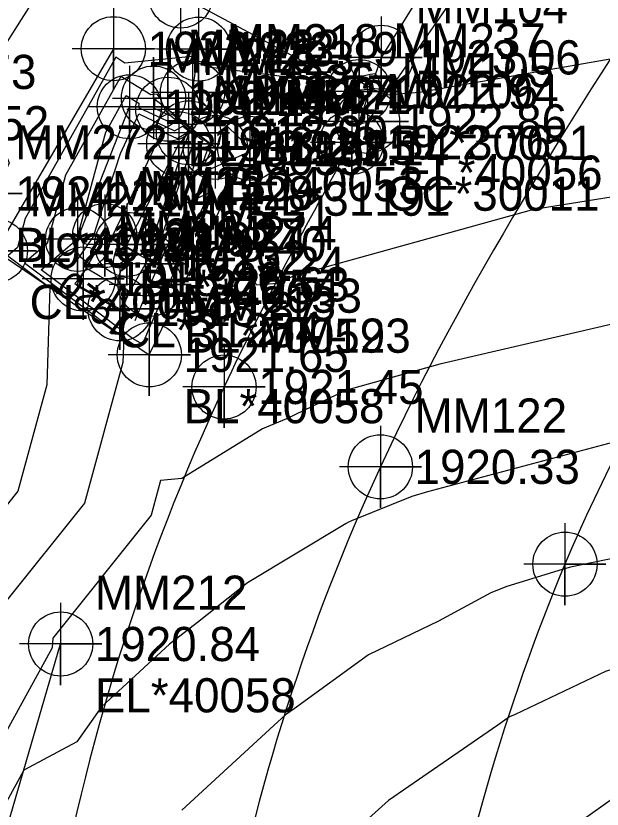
# Model space of a CAD drawing. Extents: x 1004378 to 1005103, y 553854 to 554288.
# Drawn here: x 1005001.8 to 1005044.7, y 554194.9 to 554252.9 of the extents above; entities that cross this region are included whole.
import ezdxf

# ---------------------------------------------------------------- set-up
doc = ezdxf.new("R2010")
doc.units = 0
for name, color, linetype in [('DTM Contours Major', 7, 'Continuous'), ('DTM Contours Major Text', 7, 'Continuous'), ('DTM Contours Minor', 7, 'Continuous'), ('Exist DTM Breakline', 7, 'Continuous'), ('Exist DTM Breakline Cogo Comment', 7, 'Continuous'), ('Exist DTM Breakline Cogo Elevation', 7, 'Continuous'), ('Exist DTM Breakline Cogo Number', 7, 'Continuous'), ('Exist DTM Breakline Cogo Point CELL', 7, 'Continuous'), ('Exist DTM Crownline', 7, 'Continuous'), ('Exist DTM Crownline Cogo Elevation', 7, 'Continuous'), ('Exist DTM Crownline Cogo Number', 7, 'Continuous'), ('Exist DTM Crownline Cogo Point CELL', 7, 'Continuous'), ('Exist DTM Regular Point Cogo Elevation', 7, 'Continuous'), ('Exist DTM Regular Point Cogo Number', 7, 'Continuous'), ('Exist DTM Spot Elevation Cogo Elevation', 7, 'Continuous'), ('Exist DTM Spot Elevation Cogo Number', 7, 'Continuous'), ('Exist Roads Curbs', 7, 'Continuous'), ('Exist Roads EOP', 7, 'Continuous'), ('Exist Roads EOP Cogo Comment', 7, 'Continuous'), ('Exist Roads EOP Cogo Elevation', 7, 'Continuous'), ('Exist Roads EOP Cogo Number', 7, 'Continuous'), ('Exist Roads EOP Cogo Point CELL', 7, 'Continuous'), ('Exist Roads Soil', 7, 'Continuous'), ('Exist Roads Soil Cogo Comment', 7, 'Continuous'), ('Exist Roads Soil Cogo Elevation', 7, 'Continuous'), ('Exist Roads Soil Cogo Number', 7, 'Continuous'), ('Exist Roads Soil Cogo Point CELL', 7, 'Continuous'), ('Exist Structure Major Bridge WW Cogo Comment', 7, 'Continuous'), ('Exist Structure Major Bridge WW Cogo Elevation', 7, 'Continuous'), ('Exist Structure Major Bridge WW Cogo Number', 7, 'Continuous'), ('Exist Structure Major Bridge WW Cogo Point CELL', 7, 'Continuous'), ('Exist Structure Minor Drop Inlet Cogo Comment', 7, 'Continuous'), ('Exist Structure Minor Drop Inlet Cogo Elevation', 7, 'Continuous'), ('Exist Structure Minor Drop Inlet Cogo Number', 7, 'Continuous'), ('Exist Structure Minor Drop Inlet Cogo Point CELL', 7, 'Continuous')]:
    doc.layers.add(name, color=color, linetype=linetype)

msp = doc.modelspace()

# ---------------------------------------------------------------- linework, layer by layer
at = {"layer": 'DTM Contours Major'}
for points in [[(1005005.579, 554234.428), (1005006.321, 554235.061), (1005007.473, 554236.739), (1005009.471, 554242.852), (1005010.83, 554245.746)], [(1005010.83, 554245.746), (1005013.438, 554244.516), (1005014.032, 554244.854), (1005015.001, 554244.074), (1005014.744, 554243.464), (1005012.475, 554236.752), (1005013.363, 554237.145), (1005011.504, 554232.95), (1005010.522, 554230.625)], [(1005085.253, 554232.251), (1005065.7, 554222.397), (1005064.933, 554221.918), (1005064.991, 554222.066), (1005065.344, 554223.049), (1005065.952, 554224.718), (1005066.048, 554225.004), (1005062.678, 554224.698), (1005047.268, 554222.206), (1005031.925, 554218.126), (1005030.77, 554217.777), (1005026.361, 554215.994), (1005026.142, 554215.905), (1005025.965, 554215.797), (1005018.761, 554211.473), (1005015.099, 554208.571), (1005013.055, 554206.965), (1005008.097, 554202.389), (1005006.285, 554199.827), (1005002.41, 554197.77), (1005001.113, 554195.406)]]:
    msp.add_lwpolyline(points, dxfattribs=at)
at = {"layer": 'DTM Contours Minor'}
for points in [[(1005049.674, 554261.493), (1005048.336, 554262.162), (1005048.391, 554261.154), (1005047.971, 554261.002), (1005047.219, 554261.151), (1005038.078, 554260.42), (1005037.81, 554261.029), (1005038.533, 554264.244), (1005038.474, 554264.547), (1005022.134, 554266.393), (1005018.739, 554266.663), (1005008.512, 554259.857), (1005006.97, 554257.736), (1005007.666, 554257.334), (1005003.478, 554254.686), (1004999.082, 554247.727), (1005001.345, 554242.184), (1004999.666, 554238.402), (1004998.854, 554234.12), (1004998.544, 554224.321), (1004997.101, 554219.058), (1004994.148, 554215.354), (1004993.153, 554201.493), (1004985.717, 554187.945)], [(1005045.835, 554249.855), (1005031.335, 554247.323), (1005028.865, 554247.126), (1005028.25, 554248.522), (1005028.121, 554248.671), (1005027.728, 554248.629), (1005025.559, 554248.116), (1005024.184, 554248.111), (1005015.878, 554249.159), (1005015.053, 554249.514), (1005014.698, 554249.961), (1005009.806, 554249.475), (1005009.131, 554249.89), (1005002.516, 554238.096), (1005001.94, 554235.973), (1005001.24, 554235.376), (1005004.325, 554233.049), (1005004.1, 554225.944), (1005001.971, 554218.176), (1004997.612, 554212.709), (1004996.931, 554203.23), (1004987.915, 554186.802)], [(1005058.295, 554241.729), (1005039.877, 554238.78), (1005039.335, 554238.654), (1005022.102, 554233.882), (1005020.992, 554233.342), (1005019.427, 554233.237), (1005016.782, 554238.803), (1005018.564, 554242.826), (1005015.241, 554241.355), (1005015.916, 554243.352), (1005015.992, 554243.533), (1005013.267, 554245.727), (1005013.091, 554245.626), (1005011.963, 554246.158), (1005012.004, 554246.821), (1005012.332, 554246.974), (1005012.153, 554247.198), (1005011.692, 554247.152), (1005009.516, 554248.491), (1005005.462, 554241.262), (1005004.108, 554236.273), (1005002.462, 554234.869), (1005009.715, 554229.399), (1005009.657, 554227.567), (1005006.84, 554217.294), (1005001.076, 554210.065)], [(1005013.264, 554245.071), (1005013.649, 554245.29), (1005015.496, 554243.804), (1005015.33, 554243.408), (1005013.858, 554239.054), (1005015.963, 554239.985), (1005011.554, 554230.034), (1005011.084, 554228.92), (1005010.348, 554229.337), (1005003.685, 554234.362), (1005006.277, 554236.572), (1005008.408, 554244.428), (1005009.901, 554247.092), (1005010.821, 554246.526), (1005010.803, 554246.232), (1005013.264, 554245.071)], [(1005009.801, 554238.687), (1005012.52, 554244.475), (1005013.612, 554243.96), (1005014.414, 554244.418), (1005014.505, 554244.345), (1005014.159, 554243.52), (1005012.088, 554237.397), (1005010.992, 554235.429), (1005008.828, 554236.656), (1005009.801, 554238.687)], [(1005081.907, 554236.456), (1005081.575, 554236.342), (1005069.531, 554230.299), (1005070.085, 554231.824), (1005070.64, 554233.472), (1005054.504, 554232.01), (1005052.782, 554231.968), (1005051.198, 554231.714), (1005032.836, 554227.453), (1005025.92, 554225.538), (1005021.623, 554223.448), (1005019.859, 554222.732), (1005013.96, 554219.101), (1005012.402, 554218.937), (1005011.71, 554216.413), (1005004.54, 554207.42), (1005004.489, 554206.704), (1004992.311, 554184.516)], [(1005006.967, 554234.467), (1005006.297, 554233.491), (1005006.13, 554233.348), (1005006.549, 554233.032), (1005009.541, 554231.336), (1005010.106, 554232.675), (1005008.005, 554233.874), (1005006.967, 554234.467)], [(1005080.939, 554224.769), (1005067.37, 554217.93), (1005060.336, 554213.536), (1005060.866, 554214.898), (1005061.455, 554216.534), (1005042.381, 554212.616), (1005041.766, 554212.425), (1005037.72, 554211.199), (1005036.548, 554210.725), (1005032.718, 554208.659), (1005027.609, 554206.201), (1005022.187, 554202.253), (1005021.549, 554201.814), (1005020.689, 554201.039), (1005013.957, 554194.829)], [(1005076.625, 554217.286), (1005069.041, 554213.464), (1005056.52, 554205.643), (1005056.186, 554205.45), (1005055.751, 554205.106), (1005055.8, 554205.258), (1005055.916, 554205.611), (1005056.742, 554207.729), (1005056.863, 554208.065), (1005052.951, 554207.261), (1005051.317, 554206.753), (1005044.981, 554205.003), (1005038.321, 554201.832), (1005037.92, 554201.653), (1005037.066, 554201.044), (1005029.069, 554195.542), (1005025.438, 554192.269)], [(1005072.311, 554209.804), (1005070.712, 554208.998), (1005068.073, 554207.35), (1005060.854, 554203.169), (1005055.614, 554199.027), (1005051.563, 554195.07), (1005051.936, 554196.712), (1005052.473, 554198.935), (1005052.494, 554198.998), (1005052.502, 554199.025), (1005052.396, 554198.996), (1005052.336, 554198.967), (1005046.282, 554196.261), (1005040.238, 554191.952)]]:
    msp.add_lwpolyline(points, dxfattribs=at)
at = {"layer": 'Exist DTM Breakline'}
msp.add_line((1005041.953, 554266.011), (1005027.535, 554245.207), dxfattribs=at)
for points in [[(1005011.587, 554228.131), (1005018.939, 554243.236), (1005014.748, 554247.317), (1005015.189, 554250.493), (1005008.958, 554250.519), (1005000.334, 554235.751), (1005011.587, 554228.131)], [(1005011.889, 554246.911), (1005012.944, 554246.095), (1005016.412, 554243.304)], [(1005006.344, 554236.582), (1005010.126, 554246.275)], [(1005014.454, 554244.373), (1005013.737, 554243.561), (1005009.944, 554236.21)], [(1004987.71, 553883.194), (1004993.763, 553908.865), (1004995.956, 553952.192), (1004996.06, 553992.449), (1004993.928, 554035.876), (1004994.309, 554070.389), (1004993.033, 554080.737), (1004990.275, 554106.198), (1004991.435, 554130.882), (1004994.664, 554165.005), (1004997.714, 554181.706), (1005005.106, 554206.988)]]:
    msp.add_lwpolyline(points, dxfattribs=at)
msp.add_lwpolyline([(1005009.438, 554231.497), (1005011.467, 554235.075), (1005008.323, 554236.858), (1005006.294, 554233.28)], close=True, dxfattribs=at)
msp.add_spline([(1005062.556, 554249.275), (1005041.97, 554212.824), (1005032.11, 554179.915), (1005026.833, 554146.301), (1005025.779, 554104.318), (1005027.497, 554055.674)], degree=3, dxfattribs=at)
at = {"layer": 'Exist DTM Breakline Cogo Point CELL'}
for points in [[(1005008.958, 554253.519), (1005008.958, 554247.519), (1005008.958, 554250.519), (1005011.958, 554250.519), (1005005.958, 554250.519)], [(1005015.189, 554253.493), (1005015.189, 554247.493), (1005015.189, 554250.493), (1005018.189, 554250.493), (1005012.189, 554250.493)], [(1005014.748, 554250.317), (1005014.748, 554244.317), (1005014.748, 554247.317), (1005017.748, 554247.317), (1005011.748, 554247.317)], [(1005010.126, 554249.275), (1005010.126, 554243.275), (1005010.126, 554246.275), (1005013.126, 554246.275), (1005007.126, 554246.275)], [(1005027.535, 554248.207), (1005027.535, 554242.207), (1005027.535, 554245.207), (1005030.535, 554245.207), (1005024.535, 554245.207)], [(1005014.454, 554247.373), (1005014.454, 554241.373), (1005014.454, 554244.373), (1005017.454, 554244.373), (1005011.454, 554244.373)], [(1005013.737, 554246.561), (1005013.737, 554240.561), (1005013.737, 554243.561), (1005016.737, 554243.561), (1005010.737, 554243.561)], [(1005018.939, 554246.236), (1005018.939, 554240.236), (1005018.939, 554243.236), (1005021.939, 554243.236), (1005015.939, 554243.236)], [(1004999.282, 554242.926), (1004999.282, 554236.926), (1004999.282, 554239.926), (1005002.282, 554239.926), (1004996.282, 554239.926)], [(1005006.344, 554239.582), (1005006.344, 554233.582), (1005006.344, 554236.582), (1005009.344, 554236.582), (1005003.344, 554236.582)], [(1005000.334, 554238.751), (1005000.334, 554232.751), (1005000.334, 554235.751), (1005003.334, 554235.751), (1004997.334, 554235.751)], [(1005009.944, 554239.21), (1005009.944, 554233.21), (1005009.944, 554236.21), (1005012.944, 554236.21), (1005006.944, 554236.21)], [(1005011.643, 554236.289), (1005011.643, 554230.289), (1005011.643, 554233.289), (1005014.643, 554233.289), (1005008.643, 554233.289)], [(1005011.587, 554231.131), (1005011.587, 554225.131), (1005011.587, 554228.131), (1005014.587, 554228.131), (1005008.587, 554228.131)], [(1005041.97, 554215.824), (1005041.97, 554209.824), (1005041.97, 554212.824), (1005044.97, 554212.824), (1005038.97, 554212.824)], [(1005005.106, 554209.988), (1005005.106, 554203.988), (1005005.106, 554206.988), (1005008.106, 554206.988), (1005002.106, 554206.988)]]:
    msp.add_lwpolyline(points, dxfattribs=at)
for centre in [(1005008.958, 554250.519), (1005015.189, 554250.493), (1005014.748, 554247.317), (1005010.126, 554246.275), (1005027.535, 554245.207), (1005014.454, 554244.373), (1005013.737, 554243.561), (1005018.939, 554243.236), (1005006.344, 554236.582), (1005009.944, 554236.21), (1005000.334, 554235.751), (1005011.643, 554233.289), (1005011.587, 554228.131), (1005041.97, 554212.824), (1005005.106, 554206.988)]:
    msp.add_circle(centre, 2.344, dxfattribs=at)
at = {"layer": 'Exist DTM Crownline'}
msp.add_spline([(1005050.587, 554258.044), (1005028.479, 554219.945), (1005017.046, 554183.931), (1005013.967, 554147.492), (1005013.771, 554103.753), (1005015.769, 554055.214)], degree=3, dxfattribs=at)
at = {"layer": 'Exist DTM Crownline Cogo Point CELL'}
msp.add_lwpolyline([(1005028.479, 554222.945), (1005028.479, 554216.945), (1005028.479, 554219.945), (1005031.479, 554219.945), (1005025.479, 554219.945)], dxfattribs=at)
msp.add_circle((1005028.479, 554219.945), 2.344, dxfattribs=at)
at = {"layer": 'Exist Roads Curbs'}
msp.add_spline([(1005075.03, 554240.325), (1005055.961, 554205.561), (1005046.997, 554176.639), (1005041.862, 554143.203), (1005041.439, 554133.575)], degree=3, dxfattribs=at)
at = {"layer": 'Exist Roads EOP'}
msp.add_lwpolyline([(1005042.326, 554267.369), (1005036.922, 554263.41), (1005028.544, 554249.886), (1005026.381, 554243.671)], dxfattribs=at)
for points in [[(1005026.381, 554243.671), (1005017.049, 554225.785), (1005004.478, 554185.698), (1005001.445, 554147.868), (1005001.025, 554103.612), (1005002.785, 554054.517)], [(1005074.494, 554240.581), (1005055.678, 554205.88), (1005046.35, 554176.623), (1005041.386, 554143.248), (1005040.93, 554132.857)]]:
    msp.add_spline(points, degree=3, dxfattribs=at)
at = {"layer": 'Exist Roads EOP Cogo Point CELL'}
for points in [[(1005028.544, 554252.886), (1005028.544, 554246.886), (1005028.544, 554249.886), (1005031.544, 554249.886), (1005025.544, 554249.886)], [(1005026.381, 554246.671), (1005026.381, 554240.671), (1005026.381, 554243.671), (1005029.381, 554243.671), (1005023.381, 554243.671)], [(1005017.049, 554228.785), (1005017.049, 554222.785), (1005017.049, 554225.785), (1005020.049, 554225.785), (1005014.049, 554225.785)]]:
    msp.add_lwpolyline(points, dxfattribs=at)
for centre in [(1005028.544, 554249.886), (1005026.381, 554243.671), (1005017.049, 554225.785)]:
    msp.add_circle(centre, 2.344, dxfattribs=at)
at = {"layer": 'Exist Roads Soil'}
msp.add_lwpolyline([(1005026.922, 554247.386), (1005013.881, 554254.375), (1004980.46, 554270.626), (1004959.228, 554275.018)], dxfattribs=at)
at = {"layer": 'Exist Roads Soil Cogo Point CELL'}
for points in [[(1005013.881, 554251.375), (1005013.881, 554257.375), (1005013.881, 554254.375), (1005016.881, 554254.375), (1005010.881, 554254.375)], [(1005026.922, 554244.386), (1005026.922, 554250.386), (1005026.922, 554247.386), (1005029.922, 554247.386), (1005023.922, 554247.386)]]:
    msp.add_lwpolyline(points, dxfattribs=at)
for centre in [(1005013.881, 554254.375), (1005026.922, 554247.386)]:
    msp.add_circle(centre, 2.344, dxfattribs=at)
at = {"layer": 'Exist Structure Major Bridge WW Cogo Point CELL'}
for points in [[(1005008.889, 554246.911), (1005014.889, 554246.911), (1005011.889, 554246.911), (1005011.889, 554249.911), (1005011.889, 554243.911)], [(1005009.944, 554246.095), (1005015.944, 554246.095), (1005012.944, 554246.095), (1005012.944, 554249.095), (1005012.944, 554243.095)], [(1005013.412, 554243.304), (1005019.412, 554243.304), (1005016.412, 554243.304), (1005016.412, 554246.304), (1005016.412, 554240.304)]]:
    msp.add_lwpolyline(points, dxfattribs=at)
for centre in [(1005011.889, 554246.911), (1005012.944, 554246.095), (1005016.412, 554243.304)]:
    msp.add_circle(centre, 2.344, dxfattribs=at)
at = {"layer": 'Exist Structure Minor Drop Inlet Cogo Point CELL'}
for points in [[(1005008.323, 554239.858), (1005008.323, 554233.858), (1005008.323, 554236.858), (1005011.323, 554236.858), (1005005.323, 554236.858)], [(1005011.304, 554237.786), (1005011.304, 554231.786), (1005011.304, 554234.786), (1005014.304, 554234.786), (1005008.304, 554234.786)], [(1005006.752, 554236.683), (1005006.752, 554230.683), (1005006.752, 554233.683), (1005009.752, 554233.683), (1005003.752, 554233.683)], [(1005009.438, 554234.497), (1005009.438, 554228.497), (1005009.438, 554231.497), (1005012.438, 554231.497), (1005006.438, 554231.497)]]:
    msp.add_lwpolyline(points, dxfattribs=at)
for centre in [(1005008.323, 554236.858), (1005011.304, 554234.786), (1005006.752, 554233.683), (1005009.438, 554231.497)]:
    msp.add_circle(centre, 2.344, dxfattribs=at)

# ---------------------------------------------------------------- texts
at = {"layer": 'DTM Contours Major Text'}
msp.add_text('1920', height=2, rotation=142.43295, dxfattribs=at).set_placement((1005010.584, 554230.788))
at = {"layer": 'Exist DTM Breakline Cogo Comment'}
for s, p in [('EL*40059', (1005012.626, 554241.275)), ('EL*40056', (1005030.035, 554240.207)), ('BL*40053', (1005016.954, 554239.373)), ('BL*40051', (1005001.782, 554234.926)), ('EL*40053', (1005012.444, 554231.21)), ('CL*40058', (1005002.834, 554230.751)), ('BL*40059', (1005014.143, 554228.289)), ('BL*40058', (1005014.087, 554223.131)), ('EL*40058', (1005007.606, 554201.988))]:
    msp.add_text(s, height=2.5, dxfattribs=at).set_placement(p)
at = {"layer": 'Exist DTM Breakline Cogo Elevation'}
for s, p in [('1923.45', (1005011.458, 554249.269)), ('1923.19', (1005017.689, 554249.243)), ('1922.57', (1005017.248, 554246.067)), ('1920.42', (1005012.626, 554245.025)), ('1922.86', (1005030.035, 554243.957)), ('1918.90', (1005016.954, 554243.123)), ('1918.28', (1005016.237, 554242.311)), ('1922.14', (1005021.439, 554241.986)), ('1924.15', (1005001.782, 554238.676)), ('1920.97', (1005008.844, 554235.332)), ('1923.74', (1005002.834, 554234.501)), ('1918.40', (1005012.444, 554234.96)), ('1920.63', (1005014.143, 554232.039)), ('1921.65', (1005014.087, 554226.881)), ('1920.84', (1005007.606, 554205.738))]:
    msp.add_text(s, height=2.5, dxfattribs=at).set_placement(p)
at = {"layer": 'Exist DTM Breakline Cogo Number'}
for s, p in [('MM218', (1005017.248, 554249.817)), ('MM216', (1005012.626, 554248.775)), ('MM105', (1005030.035, 554247.707)), ('MM226', (1005016.954, 554246.873)), ('MM227', (1005016.237, 554246.061)), ('MM217', (1005021.439, 554245.736)), ('MM272', (1005001.782, 554242.426)), ('MM215', (1005008.844, 554239.082)), ('MM228', (1005012.444, 554238.71)), ('MM221', (1005002.834, 554238.251)), ('MM214', (1005014.143, 554235.789)), ('MM213', (1005014.087, 554230.631)), ('MM212', (1005007.606, 554209.488))]:
    msp.add_text(s, height=2.5, dxfattribs=at).set_placement(p)
at = {"layer": 'Exist DTM Crownline Cogo Elevation'}
msp.add_text('1920.33', height=2.5, dxfattribs=at).set_placement((1005030.979, 554218.695))
at = {"layer": 'Exist DTM Crownline Cogo Number'}
msp.add_text('MM122', height=2.5, dxfattribs=at).set_placement((1005030.979, 554222.445))
at = {"layer": 'Exist DTM Regular Point Cogo Elevation'}
msp.add_text('1924.52', height=2.5, dxfattribs=at).set_placement((1004992.187, 554243.822))
at = {"layer": 'Exist DTM Regular Point Cogo Number'}
msp.add_text('MM273', height=2.5, dxfattribs=at).set_placement((1004992.187, 554247.572))
at = {"layer": 'Exist DTM Spot Elevation Cogo Elevation'}
msp.add_text('1918.40', height=2.5, dxfattribs=at).set_placement((1005012.444, 554234.96))
at = {"layer": 'Exist DTM Spot Elevation Cogo Number'}
msp.add_text('MM229', height=2.5, dxfattribs=at).set_placement((1005012.444, 554238.71))
at = {"layer": 'Exist Roads EOP Cogo Comment'}
msp.add_text('OC*30011', height=2.5, dxfattribs=at).set_placement((1005028.881, 554238.671))
at = {"layer": 'Exist Roads EOP Cogo Elevation'}
for s, p in [('1923.06', (1005031.044, 554248.636)), ('1922.76', (1005028.881, 554242.421)), ('1921.45', (1005019.549, 554224.535))]:
    msp.add_text(s, height=2.5, dxfattribs=at).set_placement(p)
at = {"layer": 'Exist Roads EOP Cogo Number'}
for s, p in [('MM104', (1005031.044, 554252.386)), ('MM106', (1005028.881, 554246.171)), ('MM123', (1005019.549, 554228.285))]:
    msp.add_text(s, height=2.5, dxfattribs=at).set_placement(p)
at = {"layer": 'Exist Roads Soil Cogo Comment'}
msp.add_text('BL*30051', height=2.5, dxfattribs=at).set_placement((1005029.422, 554242.386))
at = {"layer": 'Exist Roads Soil Cogo Elevation'}
msp.add_text('1922.94', height=2.5, dxfattribs=at).set_placement((1005029.422, 554246.136))
at = {"layer": 'Exist Roads Soil Cogo Number'}
msp.add_text('MM237', height=2.5, dxfattribs=at).set_placement((1005029.422, 554249.886))
at = {"layer": 'Exist Structure Major Bridge WW Cogo Comment'}
for s, p in [('BL*31191', (1005014.389, 554241.911)), ('EL*31191', (1005018.912, 554238.304))]:
    msp.add_text(s, height=2.5, dxfattribs=at).set_placement(p)
at = {"layer": 'Exist Structure Major Bridge WW Cogo Elevation'}
for s, p in [('1921.90', (1005014.389, 554245.661)), ('1922.85', (1005015.444, 554244.845)), ('1922.85', (1005018.912, 554242.054))]:
    msp.add_text(s, height=2.5, dxfattribs=at).set_placement(p)
at = {"layer": 'Exist Structure Major Bridge WW Cogo Number'}
for s, p in [('MM222', (1005014.389, 554249.411)), ('MM223', (1005015.444, 554248.595)), ('MM224', (1005018.912, 554245.804))]:
    msp.add_text(s, height=2.5, dxfattribs=at).set_placement(p)
at = {"layer": 'Exist Structure Minor Drop Inlet Cogo Comment'}
for s, p in [('BL*31254', (1005010.823, 554231.858)), ('CL*31254', (1005009.252, 554228.683))]:
    msp.add_text(s, height=2.5, dxfattribs=at).set_placement(p)
at = {"layer": 'Exist Structure Minor Drop Inlet Cogo Elevation'}
for s, p in [('1919.27', (1005010.823, 554235.608)), ('1919.24', (1005013.804, 554233.536)), ('1918.86', (1005009.252, 554232.433)), ('1918.87', (1005011.938, 554230.247))]:
    msp.add_text(s, height=2.5, dxfattribs=at).set_placement(p)
at = {"layer": 'Exist Structure Minor Drop Inlet Cogo Number'}
for s, p in [('MM230', (1005010.823, 554239.358)), ('MM231', (1005013.804, 554237.286)), ('MM233', (1005009.252, 554236.183)), ('MM232', (1005011.938, 554233.997))]:
    msp.add_text(s, height=2.5, dxfattribs=at).set_placement(p)

doc.saveas('drawing.dxf')
